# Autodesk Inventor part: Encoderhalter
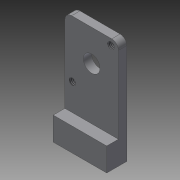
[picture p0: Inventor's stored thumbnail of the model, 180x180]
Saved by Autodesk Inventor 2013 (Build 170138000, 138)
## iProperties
Created: 2012-07
Part Number: Encoderhalter
Material: Allgemein
Document SubType Name: Modeling
Designer: rYan
Density: 1 g/cm^3
Mass: 1.52817 g
Surface Area: 15.8182 cm^2
Volume: 1.52817 cm^3
Author: rYan
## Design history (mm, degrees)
sketch "Skizze1"
  geometry: L1 (0, 0)-(0, 7); L2 (0, 7)-(3.5, 7); L3 (3.5, 7)-(3.5, 32); L4 (3.5, 32)-(6, 32); L5 (6, 32)-(6, 0); L6 (6, 0)-(0, 0)
  constraints: 12 end point, 4 parallel, 1 perpendicular, 1 vertical
  dimensions: "d0" = 6 distance between parallel lines of L5 L1; "d2" = 2.5 distance of L3.end L4.end; "d3" = 7 distance between parallel lines of L6 L2; "d4" = 32 distance between parallel lines of L6 L4
extrude "Extrusion1" new body sketch "Skizze1" distance "d5" = 16; taper "d6" = 0 deg
sketch "Skizze2"
  geometry: L1 (0, 0)-(16, 0) reference; L2 (8, 0)-(8, 35.6); L3 (0, 32)-(16, 32) reference; 1 further point
  constraints: 2 end point, 1 midpoint, 1 perpendicular, 1 point on line
  dimensions: "d7" = 22.6 distance from line of L3 point (8, 9.4)
hole "Bohrung1" sketch "Skizze2" at (8, 9.4) diameter "d8" = 5; stored, may be unused: countersink angle "d12" = 90 deg, drill point angle "d14" = 118 deg; dims "d9" = 6, "d10" = 4, "d11" = 2, "d13" = 8
sketch "Skizze3" dims "d15" = 19.05
  geometry: L1 (0, 25)-(16, 25) reference; L2 (8, 15.6)-(8, 25); L3 (8, 15.6)-(13.772, 23.177); C1 r 2.5 at (8, 15.6) reference; 3 further points
  constraints: 4 end point, 2 coincident, 1 midpoint, 3 other
  dimensions: "d17" = 37.3 deg angle of L3 L2
hole "Bohrung2" sketch "Skizze3" at (13.772, 23.177) diameter "d19" = 2.013; stored, may be unused: countersink angle "d23" = 90 deg, drill point angle "d25" = 118 deg; dims "d20" = 6, "d21" = 4, "d22" = 2, "d24" = 8
pattern_circular "Runde Anordnung1" dims angle "d27" = 360 deg
sketch "Skizze4"
  geometry: L1 (0, 6)-(-16, 6) reference; L2 (0, 0)-(-16, 0) reference; L3 (-8, 6)-(-8, 0); L4 (-13, 3)-(-3, 3)
  constraints: 4 end point, 2 midpoint, 1 perpendicular, 1 symmetric about line
  dimensions: "d29" = 3 distance between parallel lines of L1 L4; "d30" = 10 distance of L4.start L4.end
hole "Bohrung3" sketch "Skizze4" at (-13, 3), (-3, 3) diameter "d31" = 2.459; stored, may be unused: countersink angle "d35" = 90 deg, drill point angle "d37" = 118 deg; dims "d32" = 3, "d33" = 4, "d34" = 2, "d36" = 5.5
fillet "Rundung1" dims "d38" = 2
node "Volumenkörper1"
